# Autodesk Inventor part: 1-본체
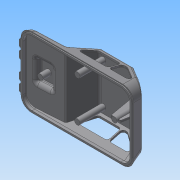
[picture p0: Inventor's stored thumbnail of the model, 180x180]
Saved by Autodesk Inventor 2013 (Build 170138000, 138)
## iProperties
Created: 2015-05
Part Number: 1-본체
Material: 일반
Document SubType Name: Modeling
Designer: Administrator
Density: 1 g/cm^3
Author: Administrator
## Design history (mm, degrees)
sketch "스케치1"
  geometry: L1 (1, -1)-(121, -1); L2 (122, 0)-(118.782, 12.011); L3 (0, 0)-(1.34, 5); L4 (1.34, 5)-(42, 7.131); L5 (56.29, 30)-(92, 30); L6 (92, 30)-(118.782, 12.011); L7 (0, 0)-(1, 0); L8 (1, 0)-(1, -1); L9 (121, -1)-(121, 0); L10 (121, 0)-(122, 0); L11 (42, 7.131)-(56.29, 30); L12 (122, 0)-(122, 10); L13 (118.782, 12.011)-(122, 10); 1 further point
  constraints: 26 end point, 4 perpendicular, 3 parallel, 1 coincident, 1 horizontal
  dimensions: "d1" = 105 deg angle of L1 L2; "d2" = 31 distance between parallel lines of L1 L5; "d9" = 42 horizontal distance of L4.end L3.start; "d10" = 1 distance of L3.start L7.end; "d11" = 1 distance of L7.end L1.start; "d12" = 6 distance from line of L3.end L1; "d14" = 105 deg angle of L3 L1; "d15" = 1 distance of L9.end L2.start; "d16" = 1 distance of L1.end L9.end; "d17" = 30 horizontal distance of L5.end L2.start; "d18" = 122 distance of L2.start L3.start; "d57" = 125 deg angle of L11 L4; "d58" = 3 deg angle of L1 L4; "d137" = 20 distance from line of L12.end L5
extrude "돌출1" new body sketch "스케치1" stored distance "d19" = 76; taper "d20" = 0 deg
node "작업 평면2"
node "작업 평면3"
node "작업 평면4"
node "작업 평면5"
sketch "스케치7"
  geometry: L1 (1, -38)-(0, -38) reference; L2 (0, -38)-(-5, -38) reference; L3 (-5, -38)-(-7.131, -38) reference; L4 (-7.131, -38)-(-7.131, 38) reference; L5 (-30, 38)-(-7.131, 38) reference; L6 (-30, -38)-(-30, 38) reference; L7 (-7.131, -38)-(-30, -38) reference; L8 (1, -38)-(1, 38) reference; L9 (1, -37)-(0, -37); L10 (0, -37)-(0, -38); L11 (0, -38)-(-30, -29.962); L12 (0, 0)-(12, 0); L13 (0, 38)-(-30, 29.962); L14 (0, 37)-(0, 38); L15 (1, 37)-(0, 37); L16 (0, -38)-(1, -38); L17 (1, -37)-(1, -38); L18 (0, -38)-(-30, -38); L19 (-30, -29.962)-(-30, -38); L20 (1, 37)-(1, 38); L21 (1, 38)-(0, 38); L22 (0, 38)-(-30, 38); L23 (-30, 38)-(-30, 29.962)
  constraints: 30 end point, 5 perpendicular, 4 symmetric about line, 3 point on line, 1 collinear
  dimensions: "d84" = 1 distance of L9.end L10.end; "d86" = 1 distance of L9.start L9.end; "d87" = 105 deg angle of L8 L11; "d88" = 105 deg angle of L8 L13
extrude "돌출5" cut sketch "스케치7" stored distance "d89" = 5; taper "d90" = 0 deg
sketch "스케치8"
  geometry: L1 (9.4, 23.66)-(29.4, 23.66); L2 (29.4, 23.66)-(29.4, 49.66); L3 (29.4, 49.66)-(9.4, 49.66); L4 (9.4, 49.66)-(9.4, 23.66); L5 (-1.6, 74.66)-(-1.6, -1.34) reference; 2 further points
  constraints: 8 end point, 2 parallel, 1 horizontal, 1 horizontal alignment, 1 midpoint, 1 perpendicular
  dimensions: "d91" = 26 distance of L1.end L2.end; "d93" = 20 distance of L2.end L3.end; "d94" = 11 distance between parallel lines of L4 L5
extrude "돌출6" join sketch "스케치8" distance "d95" = 5; taper "d96" = -20 deg
fillet "모깎기5" dims "d97" = 3
fillet "모깎기6" dims "d98" = 3
fillet "모깎기7" dims "d99" = 12
feature "쉘1" dims "d42" = 2
node "작업 평면6"
sketch "스케치11"
  geometry: L1 (42, 7.131)-(56.29, 30) reference; L2 (56.29, 30)-(92, 30) reference; L3 (92, 30)-(104.647, 21.505) reference; L4 (104.647, 21.505)-(118.782, 12.011) reference; L5 (49.689, 10)-(59.062, 25); L6 (59.062, 25)-(90.477, 25); L7 (11.591, 0)-(110.409, 0) reference; L8 (109, -1)-(13, -1) reference; L9 (112.808, 10)-(49.689, 10); L10 (83.689, 10)-(83.689, 25); L11 (84.808, 10)-(84.808, 25); L12 (112.808, 10)-(90.477, 25); 1 further point
  constraints: 12 end point, 4 point on line, 3 parallel, 2 perpendicular
  dimensions: "d126" = 5 distance between parallel lines of L1 L5; "d128" = 5 distance between parallel lines of L2 L6; "d129" = 15 distance between parallel lines of L9 L6; "d135" = 34 distance from line of L10 L5.start; "d136" = 28 distance from line of L11 L9.start; "d138" = 5 distance between parallel lines of L3 L12
extrude "돌출8" cut sketch "스케치11" stored distance "d139" = 5; taper "d140" = 0 deg
node "작업 평면7"
sketch "스케치12"
  geometry: L1 (0, 0)-(17.273, 0); A1 r 4 centre (0, -21) between (0, -17) and (0, -25); A2 r 4 centre (0, -10) between (0, -6) and (0, -14); A3 r 4 centre (0, 10) between (0, 14) and (0, 6); A4 r 4 centre (0, 21) between (0, 25) and (0, 17); 2 further points
  constraints: 8 point on circle, 4 centre point, 3 equal radius, 2 end point, 1 horizontal, 13 other
  dimensions: "d142" = 20 distance of A3.centre A2.centre; "d144" = 10 distance from line of L1 A2.centre; "d145" = 11 distance of A2.centre A1.centre; "d146" = 11 distance of A4.centre A3.centre; "d149" = 4 radius of A1
extrude "돌출9" join sketch "스케치12" stored distance "d150" = 5; taper "d151" = 0 deg
chamfer "모따기2" distance "d152" = 1; stored, may be unused: second distance "d153" = 2, angle "d154" = 45 deg
fillet "모깎기8" dims "d155" = 3
fillet "모깎기9" dims "d156" = 3
sketch "스케치13"
  geometry: L1 (65.71, 3.553)-(65.71, 56.37) reference; 3 further points
  constraints: 1 horizontal alignment, 1 midpoint, 1 other
  dimensions: "d157" = 50 distance from line of L1 point (15.71, 29.962)
feature "엠보싱1" sketch "스케치13" dims "d1" = 105 deg, "d2" = 31, "d9" = 42, "d10" = 1, "d11" = 1, "d12" = 6, "d14" = 105 deg, "d15" = 1, "d16" = 1, "d17" = 30, "d18" = 122, "d57" = 125 deg, "d58" = 3 deg, "d137" = 20, "d158" = 0.5, "d159" = 0
node "작업 평면10"
node "작업 평면11"
sketch "스케치17"
  geometry: L1 (109, -10.591)-(109, -63.409) reference; L2 (-39.8, -37)-(133.8, -37) reference; C1 r 3 at (88, -37); C2 r 3 at (48, -15); C3 r 3 at (48, -59); C4 r 3 at (8, -37); 2 further points
  constraints: 4 centre point, 3 equal radius, 2 horizontal alignment, 1 midpoint, 1 point on line, 1 vertical alignment
  dimensions: "d174" = 6 diameter of C1; "d176" = 21 distance of point (109, -37) C1.centre; "d177" = 40 horizontal distance of C1.centre C2.centre; "d178" = 40 horizontal distance of C2.centre C4.centre; "d179" = 44 distance of C3.centre C2.centre; "d180" = 22 vertical distance of C3.centre point (109, -37)
extrude "돌출11" join sketch "스케치17" stored distance "d181" = 5; taper "d182" = 0 deg
fillet "모깎기10" dims "d183" = 3
fillet "모깎기11" dims "d184" = 3
fillet "모깎기13" dims "d186" = 3
sketch "스케치18"
  geometry: L1 (104, 19.53)-(98, 23.561) reference; L2 (98, 0)-(98, 23.561) reference; L3 (107.246, 19.759)-(92.759, 29.49) reference; L4 (117.848, 12.638)-(107.246, 19.759) reference; L5 (107.246, 19.759)-(117.848, 12.638) reference; L6 (92.759, 29.49)-(107.246, 19.759) reference; L7 (104, 0)-(104, 19.53) reference; L8 (96, 2)-(106, 2); L9 (106, 2)-(108.552, 16.473); L10 (92.149, 27.49)-(105.265, 18.681) reference; L11 (105.265, 18.681)-(117.044, 10.769) reference; L12 (96, 2)-(91.419, 27.981); L13 (101, 2)-(101, 35); L14 (11.591, 0)-(110.409, 0) reference; L15 (108.552, 16.473)-(91.419, 27.981); 2 further points
  constraints: 10 end point, 2 midpoint, 2 perpendicular, 2 point on line, 1 collinear, 1 vertical alignment
  dimensions: "d187" = 20 deg angle of L9 L12; "d188" = 10 deg angle of L13 L12; "d189" = 10 distance of L8.end L8.start; "d191" = 2 distance between parallel lines of L14 L8
extrude "돌출12" join sketch "스케치18" stored distance "d192" = 2; taper "d193" = 5 deg
node "솔리드1"
node "투영된 루프3"
node "투영된 루프6"
other parameters: "d32" = 61, "d49" = 0, "d65" = -2, "d83" = 61, "d100" = 0, "d127" = 15, "d141" = -2, "d172" = 0, "d173" = -1
